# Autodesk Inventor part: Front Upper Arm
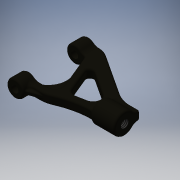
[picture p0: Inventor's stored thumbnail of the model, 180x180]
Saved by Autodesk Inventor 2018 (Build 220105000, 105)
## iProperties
Shininess: 41.0
Compacted: True
Length Units: 11272
Angle Units: 11279
Time Units: 11290
Mass Units: 11286
Length Display Precision: 3
Angle Display Precision: 2
Company: Autodesk
Created: 2001-02
Part Number: Front Upper Arm
Document SubType Name: Modeling
Designer: Autodesk, Inc.
Material: Stiffzel
Project: Inventor Samples
Density: 1.28 g/cm^3
Mass: 3.32224 g
Surface Area: 21.7649 cm^2
Volume: 2.5955 cm^3
Appearance: Stiffzel
Density: 0.0
Volumn: 0.0
Area: 0.0
PropertySet Name: Model Information
Control State: 0
Master: False
Checked Out: False
Author: Autodesk, Inc.
Revision Number: A
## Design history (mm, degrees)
sketch "Sketch1"
  geometry: C1 r 3.81 at (-5.641, -1.052)
  constraints: 1 centre point
  dimensions: "d0" = 7.62 diameter of C1
extrude "Extrusion1" new body sketch "Sketch1" distance "d1" = 6.35; taper "d2" = 0 deg
workplane "Work Plane1"
sketch "Sketch2"
  geometry: C1 r 3.81 at (0, 0) reference
extrude "Extrusion2" join sketch "Sketch2" distance "d4" = 6.35; taper "d5" = 0 deg
workaxis "Work Axis2"
workplane "Work Plane4"
sketch "Sketch10"
  geometry: L1 (-3.81, 33.02)-(3.81, 33.02) reference; L2 (-3.81, 0)-(3.81, 0) reference; L3 (5.639, 22.012)-(-38.1, 22.012); L4 (0, -12.544)-(0, 73.201) reference; L5 (-3.81, 26.67)-(3.81, 26.67) reference; L6 (-3.81, 6.35)-(3.81, 6.35) reference; L7 (0, 26.67)-(-8.001, 26.67); L8 (-38.1, 27.722)-(-38.1, 27.722); L9 (-8.001, 30.099)-(0, 30.099); L10 (0, 30.099)-(0, 26.67); L11 (-38.1, 26.013)-(-27.305, 26.013); L12 (-27.305, 26.013)-(-27.305, 15.218); L13 (-33.972, 15.218)-(-38.1, 15.218); L14 (-38.1, 15.218)-(-38.1, 26.013); L15 (-3.81, 6.35)-(-4.793, 6.35); L16 (-3.81, 0)-(-4.793, 0); L17 (-8.818, 1.203)-(-27.005, 13.136); L18 (-30.178, 15.218)-(-27.305, 15.218); L19 (-8.818, 7.553)-(-23.424, 17.136); L20 (-3.81, 6.35)-(0, 6.35); L21 (0, 0)-(0, 6.35); L22 (-3.81, 0)-(0, 0); L23 (-3.81, 30.099)-(0, 30.099); L24 (0, 30.099)-(0, 26.67); L25 (-3.81, 26.67)-(0, 26.67); A1 r 34.94 centre (-27.305, 60.952) between (-27.305, 26.013) and (-13.147, 29.01); A2 r 38.369 centre (-27.305, 60.952) between (-22.112, 22.937) and (-11.758, 25.875); A3 r 12.7 centre (-8.001, 17.399) between (-8.001, 30.099) and (-13.147, 29.01); A4 r 9.271 centre (-8.001, 17.399) between (-8.001, 26.67) and (-11.758, 25.875); A5 r 7.338 centre (-4.793, 13.688) between (-8.818, 7.553) and (-4.793, 6.35); A6 r 7.338 centre (-4.793, 7.338) between (-8.818, 1.203) and (-4.793, 0); A7 r 3.175 centre (-21.682, 19.791) between (-22.112, 22.937) and (-23.424, 17.136); A8 r 12.7 centre (-33.972, 2.518) between (-27.005, 13.136) and (-33.972, 15.218); 2 further points
  constraints: 40 end point, 18 point on circle, 13 tangent, 10 point on line, 8 centre point, 8 parallel, 5 perpendicular, 3 collinear, 3 midpoint, 2 horizontal, 1 equal radius
  dimensions: "d41" = 22.01216 distance between parallel lines of L2 L3; "d42" = 38.1 distance from line of L4 L3.end; "d43" = 3.429 distance between parallel lines of L7 L9; "d44" = 10.795 distance of L11.end L12.end; "d45" = 4.0005 distance between parallel lines of L11 L3; "d46" = 3.429 radial gap between concentric circles of A2 A1; "d47" = 12.7 radius of A3; "d48" = 10.795 distance of L12.end L13.end; "d49" = 8.001 distance from line of L4 A3.centre; "d50" = 9.271 radius of A4 (= d47 - d46); "d53" = 3.175 distance of L2.start point (-6.985, 0); "d54" = 3.175 distance of L6.start point (-6.985, 6.35) (= d53); "d57" = 4.79257 distance from line of L4 A5.centre; "d58" = 3.175 radius of A7; "d62" = 12.7 radius of A8; "d63" = 4.1275 distance from line of A8.centre L14
extrude "Extrusion7" join sketch "Sketch10" stored distance "d59" = 4.1275; taper "d60" = 0 deg
sketch "Sketch11"
  geometry: L1 (4.793, -6.35)-(12.68, -25.48); L2 (15.665, -24.392)-(8.688, -7.47); A1 r 7.338 centre (4.793, -13.688) between (8.818, -7.553) and (4.793, -6.35) reference; A2 r 38.369 centre (27.305, -60.952) between (22.112, -22.937) and (11.758, -25.875) reference; A3 r 34.94 centre (27.305, -60.952) between (27.305, -26.013) and (13.147, -29.01) reference
  constraints: 4 end point, 3 point on circle, 1 parallel, 1 point on line
  dimensions: "d64" = 3.175 distance between parallel lines of L1 L2
extrude "Extrusion8" join sketch "Sketch11" distance "d65" = 4.1275; taper "d66" = 0 deg
workaxis "Work Axis4"
fillet "Fillet5" dims "d67" = 1.5875
fillet "Fillet6" dims "d68" = 3.175
sketch "Sketch13"
  geometry: L1 (8.818, 7.553)-(23.424, 17.136) reference; L2 (14.591, 21.786)-(8.688, 7.47) reference; A1 r 7.338 centre (4.793, 13.688) between (8.688, 7.47) and (8.818, 7.553) reference; A2 r 1.587 centre (12.114, 11.614) between (10.647, 12.219) and (12.985, 10.287)
  constraints: 2 point on circle, 2 point on line, 2 tangent, 1 centre point
  dimensions: "d69" = 1.5875 radius of A2
extrude "Extrusion9" join sketch "Sketch13" distance "d70" = 4.1275; taper "d71" = 0 deg
sketch "Sketch12"
  geometry: C1 r 4.763 at (4, 2.064); 1 further point
  constraints: 1 centre point, 1 coincident
  dimensions: "d72" = 9.525 diameter of C1
extrude "Extrusion10" join sketch "Sketch12" distance "d73" = 10.541; taper "d74" = 0 deg
fillet "Fillet7" dims "d75" = 3.175
fillet "Fillet8" dims "d76" = 0.8128
fillet "Fillet9" dims "d77" = 0.8128
fillet "Fillet10" dims "d78" = 0.8128
fillet "Fillet11" dims "d79" = 1.5875
fillet "Fillet12" dims "d80" = 0.8128
fillet "Fillet13" dims "d81" = 0.8128
fillet "Fillet14" dims "d82" = 0.8128
fillet "Fillet15" dims "d83" = 1.5875
fillet "Fillet16" dims "d84" = 0.8128
sketch "Sketch14"
  geometry: A1 r 3.95 centre (0, 0) between (2.967, 2.607) and (2.967, -2.607) reference
hole "Hole1" sketch "Sketch14" at (0, 0) diameter "d85" = 3.4036; stored, may be unused: countersink angle "d89" = 60 deg, drill point angle "d91" = 118 deg; dims "d86" = 12.7, "d87" = 9.525, "d88" = 6.35, "d90" = 9.525
sketch "Sketch15"
  geometry: C1 r 2.997 at (0, 0) reference
hole "Hole2" sketch "Sketch15" at (0, 0) diameter "d92" = 3.175; stored, may be unused: countersink angle "d96" = 60 deg, drill point angle "d98" = 118 deg; dims "d93" = 12.7, "d94" = 9.525, "d95" = 6.35, "d97" = 9.525
sketch "Sketch16"
  geometry: A1 r 8.262 centre (-0.572, 18.823) between (-4.209, 26.242) and (-8.592, 16.838)
  constraints: 2 point on circle, 1 centre point
feature "Rib1" sketch "Sketch16" dims "d99" = 2.54, "d100" = 1.5875
fillet "Fillet17" dims "d101" = 0.381
fillet "Fillet18" dims "d102" = 0.7874
sketch "Sketch17"
  geometry: L1 (-4.785, 31.833)-(-10.868, 29.523)
  constraints: 2 end point
feature "Rib2" sketch "Sketch17" dims "d103" = 2.54, "d104" = 1.5875
fillet "Fillet19" dims "d105" = 0.381
fillet "Fillet20" dims "d106" = 0.7874
body "Solid1"
other parameters: "d3" = 20.32, "d6" = 90 deg, "d12" = 90 deg, "d22" = 3.29029 (derived), "d35" = 90 deg, "d37" = 0, "d38" = 0
